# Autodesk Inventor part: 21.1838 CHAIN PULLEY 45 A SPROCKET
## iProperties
Created: 2007-05
Part Number: 21.1838 CHAIN PULLEY 45 A SPROCKET
Document SubType Name: Modeling
Designer: Andy Moles
Material: Steel
Mass: 29.326 g
Surface Area: 33.1905 cm^2
Volume: 3.73579 cm^3
Density: 7.85 g/cm^3
Author: Andy Moles
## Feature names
1. Base1
